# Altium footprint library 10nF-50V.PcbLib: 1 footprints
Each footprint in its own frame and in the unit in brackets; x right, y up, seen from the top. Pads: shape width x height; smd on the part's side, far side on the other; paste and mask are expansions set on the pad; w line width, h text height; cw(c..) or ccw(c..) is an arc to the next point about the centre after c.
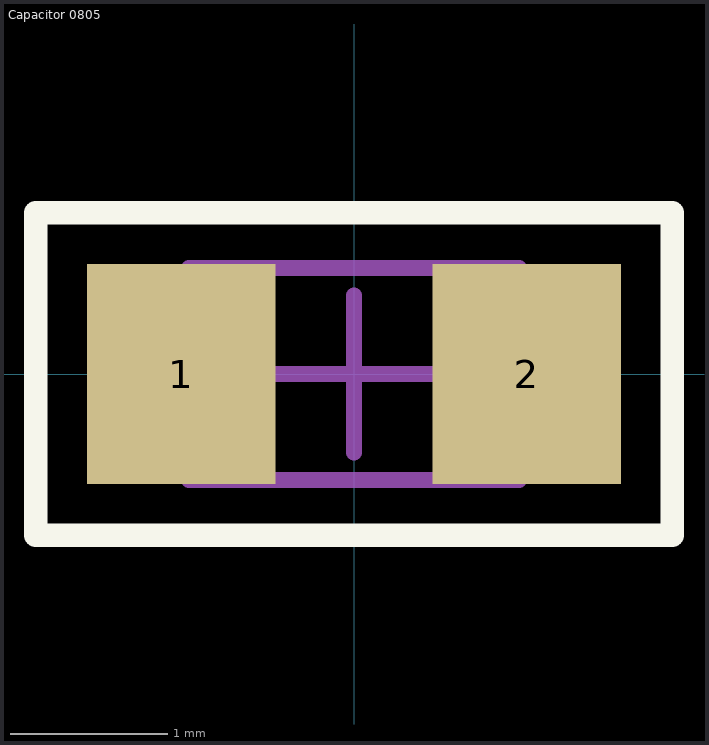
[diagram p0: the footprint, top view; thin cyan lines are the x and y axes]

## Capacitor 0805 [mm]
pads (2):
  rect 1.2x1.4 smd: 1(-1.1,0) 2(1.1,0)
Top Overlay:
  lines w0.15: -2.025,-1.025 -2.025,1.025 2.025,1.025 2.025,-1.025 -2.025,-1.025
Mechanical 13:
  lines w0.1: -1.05,-0.675 -1.05,0.675 1.05,0.675 1.05,-0.675 -1.05,-0.675
Mechanical 15:
  lines w0.1: -0.5,0 0.5,0 ; 0,-0.5 0,0.5
3D body "Cap 0805.step": height 0.6, standoff 0, extent -1,-0.625 1,0.625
